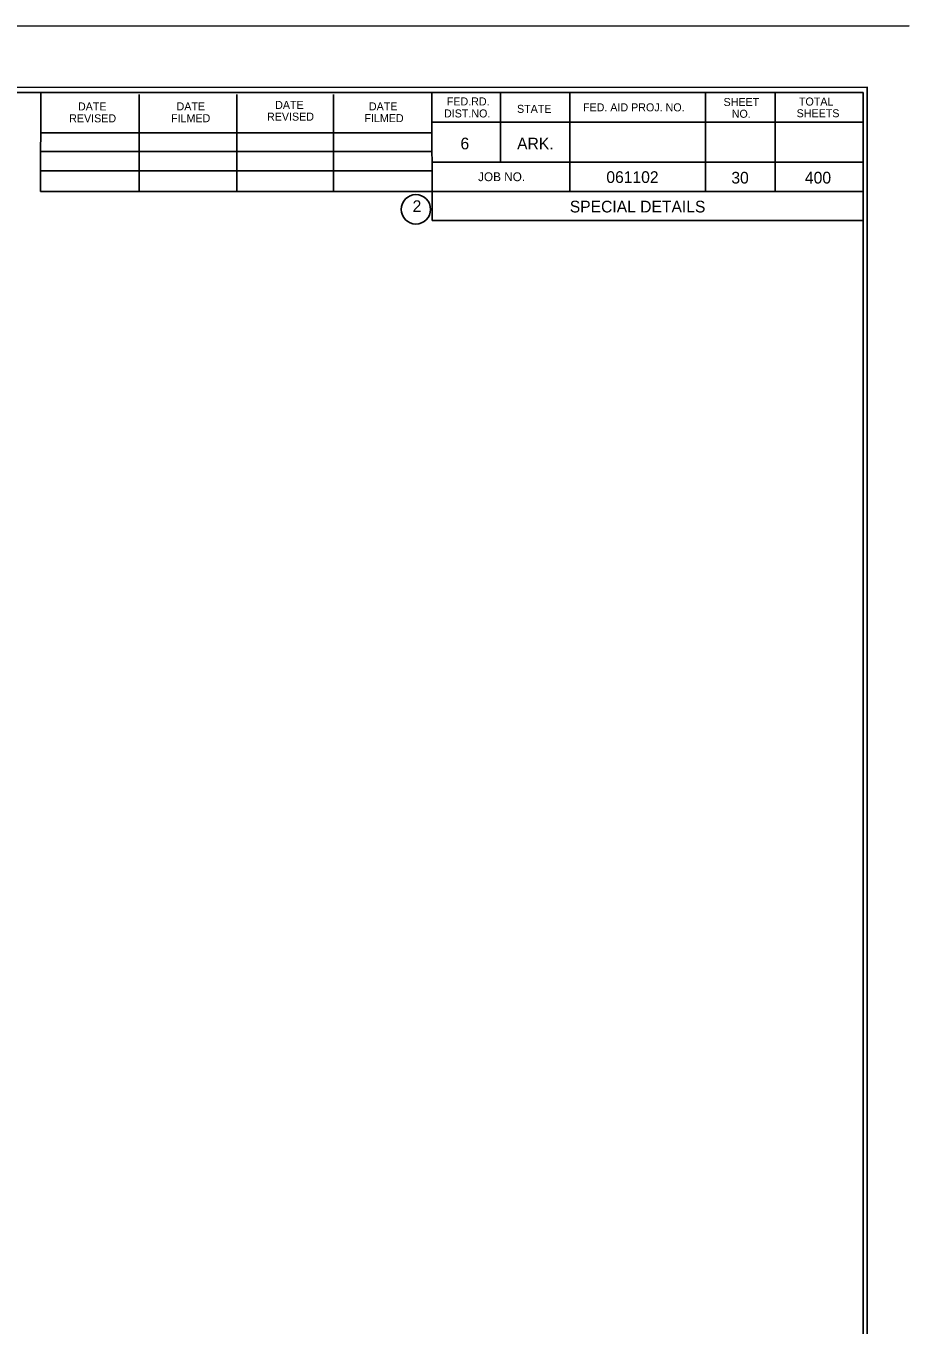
# Model space of a CAD drawing. Extents: x 714919 to 718439, y 1619644 to 1621844.
# Drawn here: x 717556 to 718439, y 1620545 to 1621844 of the extents above; entities that cross this region are included whole.
import ezdxf

# ---------------------------------------------------------------- set-up
doc = ezdxf.new("R2010")
doc.units = 0
doc.layers.add('R_Border', color=7, linetype='Continuous')
doc.layers.add('R_No Plot', color=7, linetype='Continuous')

msp = doc.modelspace()

# ---------------------------------------------------------------- linework, layer by layer
at = {"layer": 'R_Border'}
for p, q in [((718439, 1621843.8), (714919, 1621843.5)), ((715231.3, 1621777.1), (718393.1, 1621777.1)), ((717570.4, 1621678.3), (717570.5, 1621777.2)), ((717961.8, 1621777.1), (717962, 1621649.1)), ((718030.5, 1621777), (718030.4, 1621707.7)), ((718099.8, 1621777.1), (718099.8, 1621678.4)), ((718235.5, 1621777.2), (718235.5, 1621678.5)), ((718305, 1621777.3), (718305, 1621678.3)), ((718393.2, 1619722.5), (718393.1, 1621777.1)), ((717668.9, 1621678.3), (717669.1, 1621775.2)), ((717766.6, 1621678.2), (717766.6, 1621775.2)), ((717863.5, 1621678.3), (717863.5, 1621775.1)), ((718393, 1621747.5), (717962.1, 1621747.6)), ((718393.1, 1621747.9), (718393.1, 1621747.9)), ((717570.3, 1621736.9), (717961.9, 1621736.9)), ((717570.4, 1621718.3), (717961.9, 1621718.3)), ((717570.4, 1621678.3), (717570.4, 1621699)), ((717570.4, 1621699), (717962.1, 1621699)), ((718393.1, 1621707.7), (717962, 1621707.7)), ((717991.6, 1621707.7), (718393.1, 1621707.7)), ((718393.1, 1621678.3), (717570.4, 1621678.3)), ((717962, 1621649.1), (718393.1, 1621649.2))]:
    msp.add_line(p, q, dxfattribs=at)
msp.add_circle((717945.8, 1621660.4), 14.7, dxfattribs=at)
at = {"layer": 'R_No Plot'}
msp.add_lwpolyline([(715227.2, 1619717.3), (718397.1, 1619717.4), (718397.2, 1621782.5), (715227.1, 1621782.3)], close=True, dxfattribs=at)

# ---------------------------------------------------------------- texts
at = {"layer": 'R_Border'}
for s, height, rotation, p in [('DATE', 8, 0.0017, (717607.8, 1621759.3)), ('DATE', 8, 0.0017, (717706.4, 1621759.4)), ('DATE', 8, 0.0017, (717805, 1621760.8)), ('DATE', 8, 0.0017, (717898.8, 1621759.4)), ('FED.RD.', 8, 0.0017, (717976.7, 1621764.3)), ('STATE', 8, 0.0017, (718046.9, 1621756.9)), ('FED. AID PROJ. NO.', 8, 0.0017, (718112.9, 1621758.4)), ('SHEET', 8, 0.0017, (718253.5, 1621763.7)), ('TOTAL', 8, 0.0017, (718328.9, 1621764.2)), ('REVISED', 8, 0.0017, (717599, 1621747.4)), ('FILMED', 8, 0.0017, (717700.9, 1621747.5)), ('REVISED', 8, 0.0017, (717796.9, 1621749.1)), ('FILMED', 8, 0.0017, (717894.3, 1621747.6)), ('DIST.NO.', 8, 0.0017, (717973.9, 1621752.3)), ('NO.', 8, 0.0017, (718261.7, 1621752)), ('SHEETS', 8, 0.0017, (718326.6, 1621752.5)), ('6', 11.7, 0.0017, (717990.4, 1621720.4)), ('ARK.', 11.72, 0.0017, (718047, 1621720.3)), ('JOB NO.', 8.79, 0.0017, (718008, 1621688.6)), ('061102', 11.7, 0.0018, (718136.3, 1621686.8)), ('30', 11.7, 0.0018, (718261.3, 1621686.2)), ('400', 11.79, 0.0018, (718334.8, 1621686.2)), ('2', 11.7, 0.0017, (717942.5, 1621657.7)), ('SPECIAL DETAILS', 11.7, 0.0018, (718099.7, 1621657.3))]:
    msp.add_text(s, height=height, rotation=rotation, dxfattribs=at).set_placement(p)

doc.saveas('drawing.dxf')
